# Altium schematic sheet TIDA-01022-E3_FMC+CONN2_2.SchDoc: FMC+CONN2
size 431 x 279 mm; Date: Not shown in title block; ApprovedBy: Not shown in title block; CheckedBy: Not shown in title block; Author: Not shown in title block; CompanyName: Not shown in title block; DrawnBy: Avinash N; Engineer: Not shown in title block; Organization: Not shown in title block; Address1: Not shown in title block; Address2: Not shown in title block; Address3: Not shown in title block; Address4: Not shown in title block; DocumentNumber: 1; Revision: Use project parameter SCH_Rev; SheetNumber: 20; SheetTotal: 26; PageSetup: Record=PageOptions¦CenterHorizontal=True¦CenterVertical=True¦PrintScale=1.00¦XCorrection=1.00¦YCorrection=1.00¦PrintKind=0¦BorderSize=5000000¦LeftOffset=0¦BottomOffset=0¦Orientation=2¦PaperLength=1000¦PaperWidth=1000¦Scale=100¦PaperSource=15¦PrintQuality=600¦MediaType=1¦DitherType=10¦PaperKind=Letter¦PrintScaleMode=1
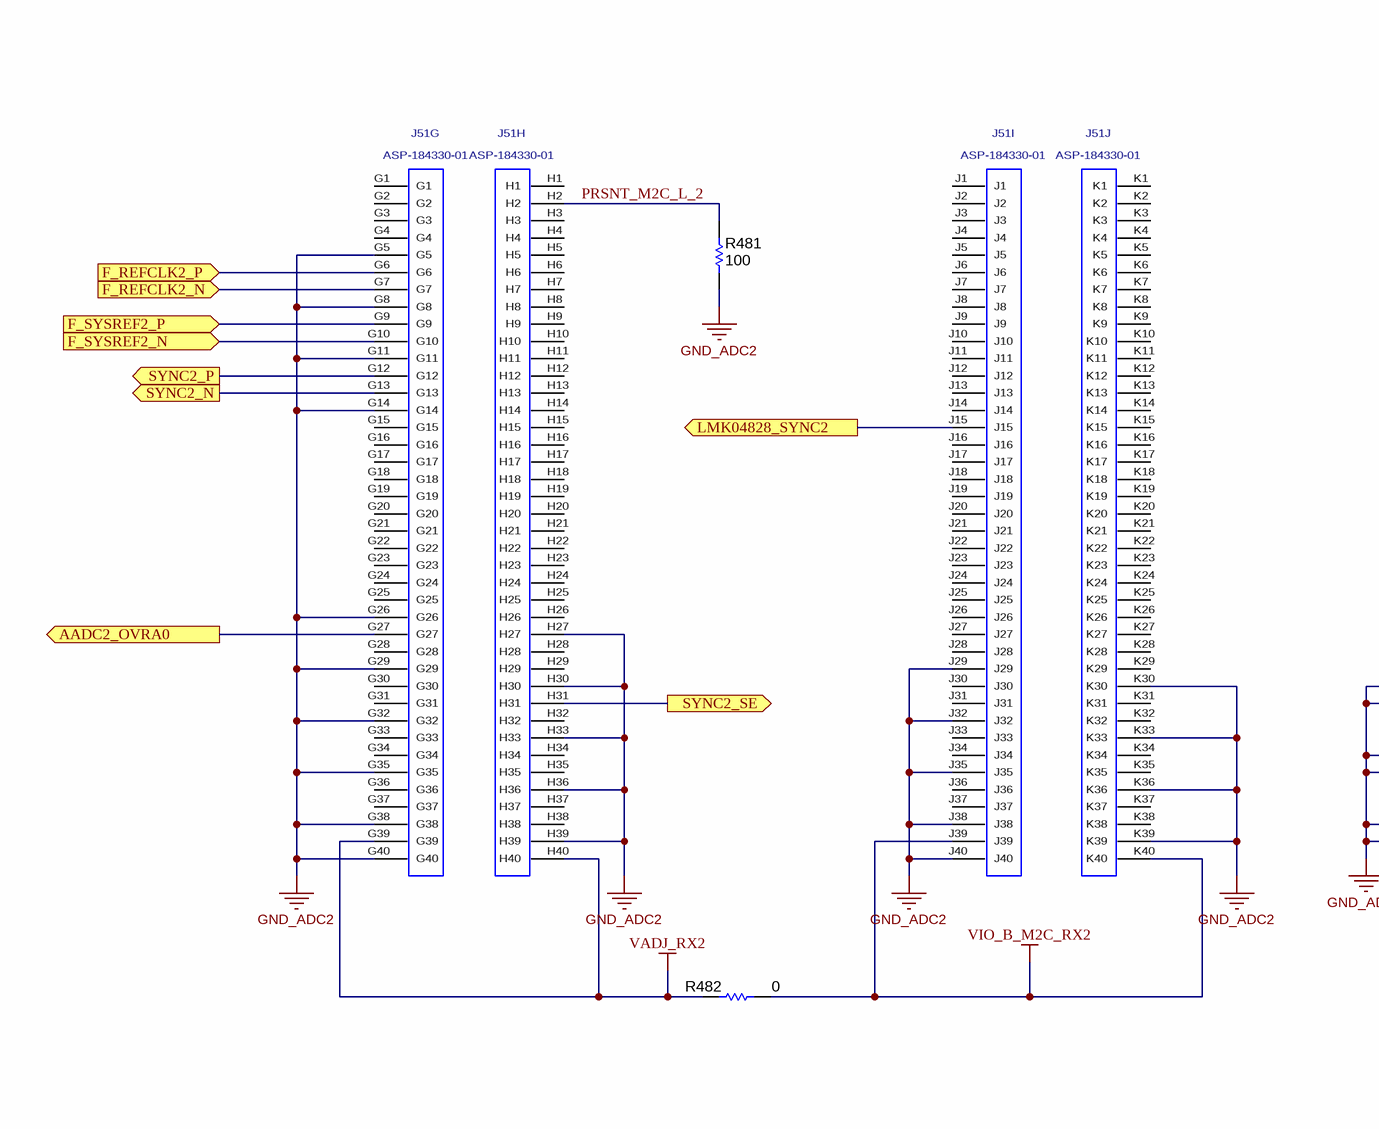
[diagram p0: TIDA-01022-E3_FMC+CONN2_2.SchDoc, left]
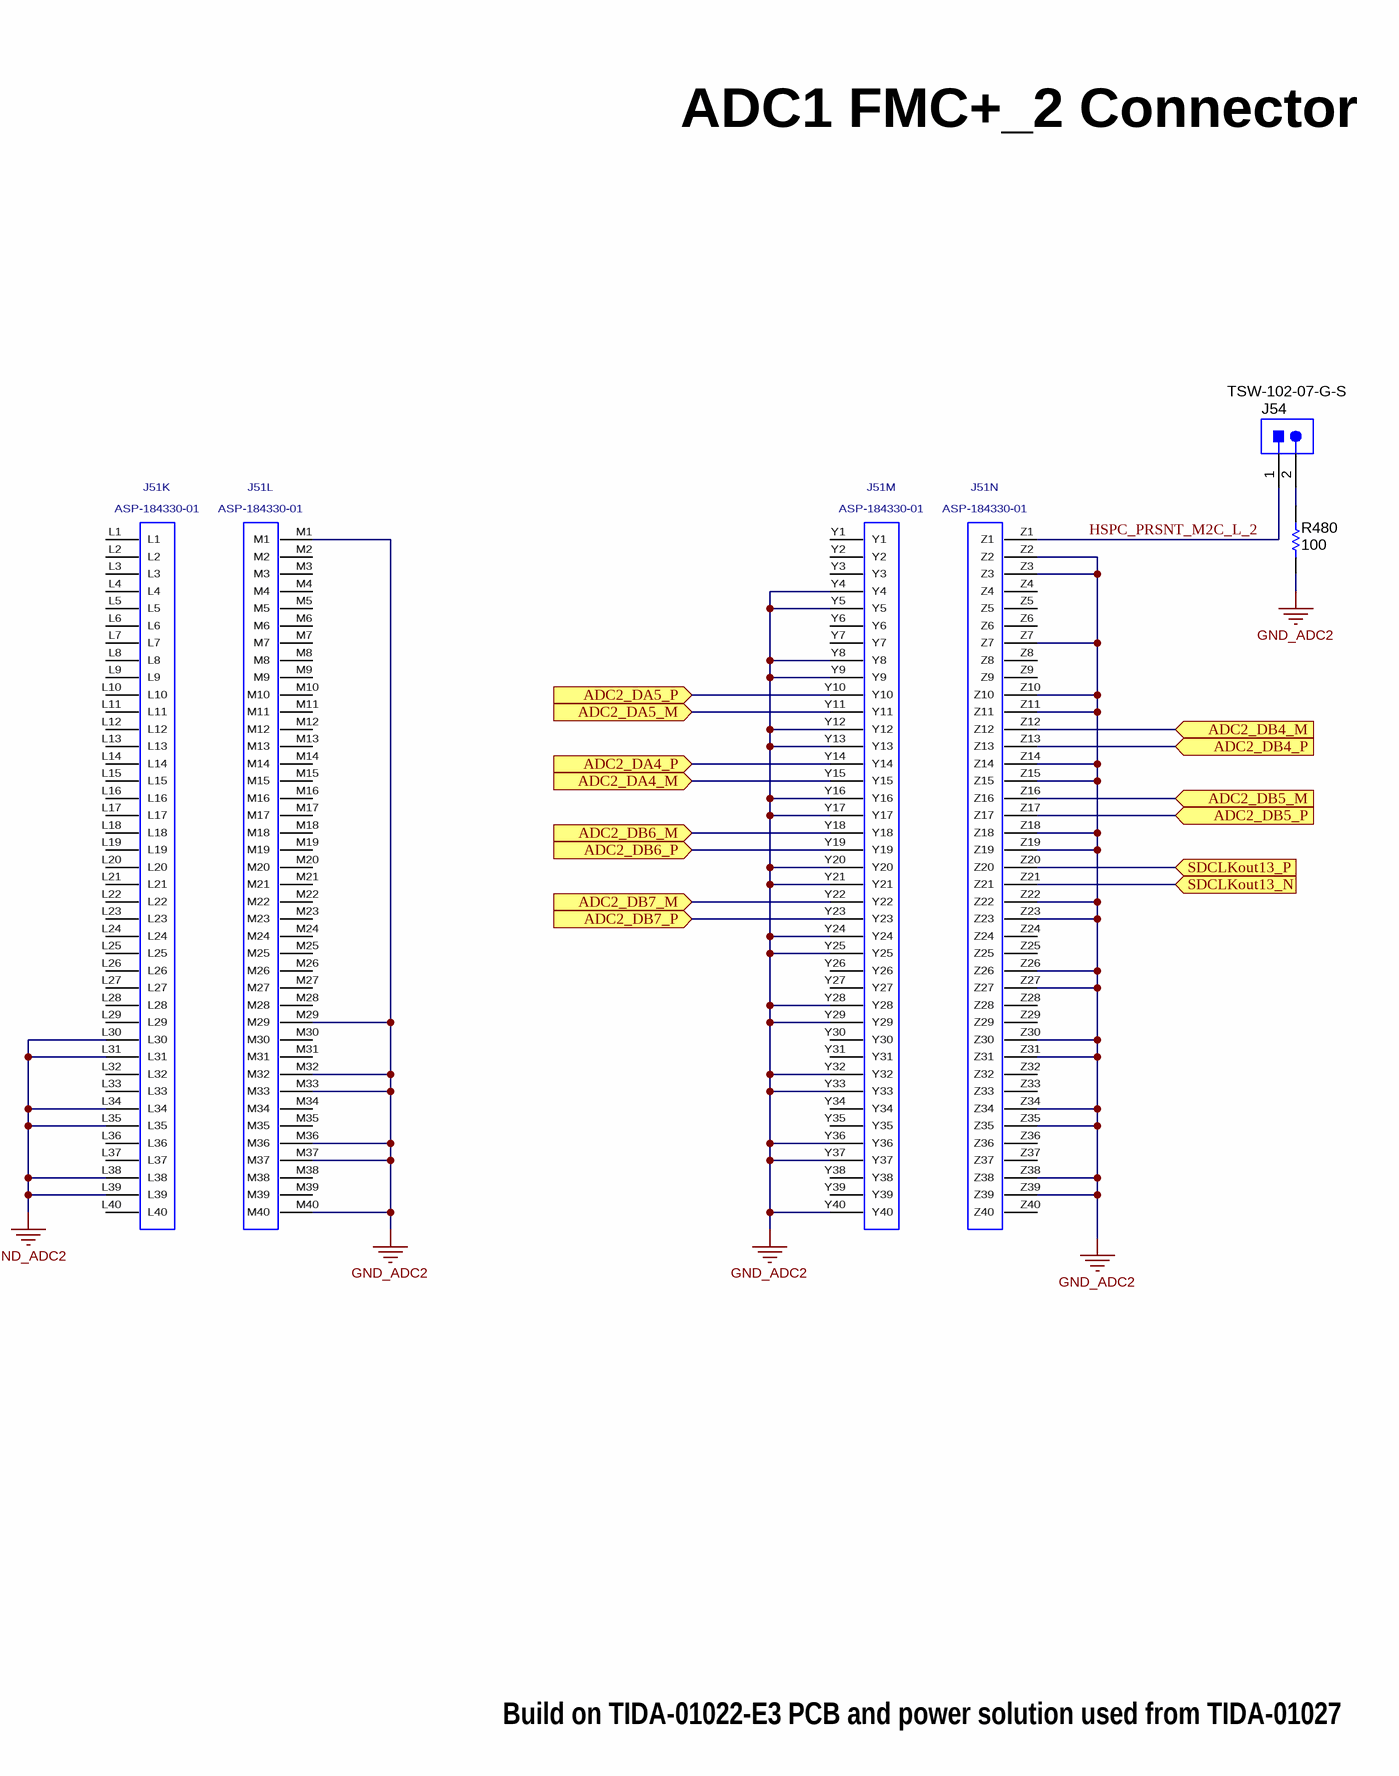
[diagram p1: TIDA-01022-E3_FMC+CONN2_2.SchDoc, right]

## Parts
J51  ASP-184330-01  [ASP-184330-01]  (parts G,H,I,J,K,L,M,N of 14)
J54  TSW-102-07-G-S  [TSW-102-07-G-S]
R480  ValueDisplayed: 100  [0402]  (hidden comment: CRCW0402100RJNED)
R481  ValueDisplayed: 100  [0402]  (hidden comment: CRCW0402100RJNED)
R482  ValueDisplayed: 0  [0402]  (hidden comment: CRCW04020000Z0ED)

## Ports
AADC2_OVRA0 (out), ADC2_DA4_M (in), ADC2_DA4_P (in), ADC2_DA5_M (in), ADC2_DA5_P (in), ADC2_DB4_M (in), ADC2_DB4_P (in), ADC2_DB5_M (in), ADC2_DB5_P (in), ADC2_DB6_M (in), ADC2_DB6_P (in), ADC2_DB7_M (in), ADC2_DB7_P (in), F_REFCLK2_N (in), F_REFCLK2_P (in), F_SYSREF2_N (in), F_SYSREF2_P (in), LMK04828_SYNC2 (out), SDCLKout13_N (in), SDCLKout13_P (in), SYNC2_N (out), SYNC2_P (out), SYNC2_SE (out)

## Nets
GND_ADC2: J51.G5 J51.G8 J51.G11 J51.G14 J51.G26 J51.G29 J51.G32 J51.G35 J51.G38 J51.G40 J51.H27 J51.H30 J51.H33 J51.H36 J51.H39 J51.J29 J51.J32 J51.J35 J51.J38 J51.J40 J51.K30 J51.K33 J51.K36 J51.K39 J51.L30 J51.L31 J51.L34 J51.L35 J51.L38 J51.L39 J51.M1 J51.M29 J51.M32 J51.M33 J51.M36 J51.M37 J51.M40 J51.Y4 J51.Y5 J51.Y8 J51.Y9 J51.Y12 J51.Y13 J51.Y16 J51.Y17 J51.Y20 J51.Y21 J51.Y24 J51.Y25 J51.Y28 J51.Y29 J51.Y32 J51.Y33 J51.Y36 J51.Y37 J51.Y40 J51.Z2 J51.Z3 J51.Z7 J51.Z10 J51.Z11 J51.Z14 J51.Z15 J51.Z18 J51.Z19 J51.Z22 J51.Z23 J51.Z26 J51.Z27 J51.Z30 J51.Z31 J51.Z34 J51.Z35 J51.Z38 J51.Z39 R480.1 R481.1
VADJ_RX2: J51.G39 J51.H40 R482.2
VIO_B_M2C_RX2: J51.J39 J51.K40 R482.1
AADC2_OVRA0: J51.G27 ; port AADC2_OVRA0
ADC2_DA4_M: J51.Y15 ; port ADC2_DA4_M
ADC2_DA4_P: J51.Y14 ; port ADC2_DA4_P
ADC2_DA5_M: J51.Y11 ; port ADC2_DA5_M
ADC2_DA5_P: J51.Y10 ; port ADC2_DA5_P
ADC2_DB4_M: J51.Z12 ; port ADC2_DB4_M
ADC2_DB4_P: J51.Z13 ; port ADC2_DB4_P
ADC2_DB5_M: J51.Z16 ; port ADC2_DB5_M
ADC2_DB5_P: J51.Z17 ; port ADC2_DB5_P
ADC2_DB6_M: J51.Y18 ; port ADC2_DB6_M
ADC2_DB6_P: J51.Y19 ; port ADC2_DB6_P
ADC2_DB7_M: J51.Y22 ; port ADC2_DB7_M
ADC2_DB7_P: J51.Y23 ; port ADC2_DB7_P
F_REFCLK2_N: J51.G7 ; port F_REFCLK2_N
F_REFCLK2_P: J51.G6 ; port F_REFCLK2_P
F_SYSREF2_N: J51.G10 ; port F_SYSREF2_N
F_SYSREF2_P: J51.G9 ; port F_SYSREF2_P
HSPC_PRSNT_M2C_L_2: J51.Z1 J54.1
LMK04828_SYNC2: J51.J15 ; port LMK04828_SYNC2
PRSNT_M2C_L_2: J51.H2 R481.2
SDCLKout13_N: J51.Z21 ; port SDCLKout13_N
SDCLKout13_P: J51.Z20 ; port SDCLKout13_P
SYNC2_N: J51.G13 ; port SYNC2_N
SYNC2_P: J51.G12 ; port SYNC2_P
SYNC2_SE: J51.H31 ; port SYNC2_SE
NetJ54_2: J54.2 R480.2

Not connected (* = marked no-connect by the designer): J51 G1 G2 G3 G4 G15 G16 G17 G18 G19 G20 G21 G22 G23 G24 G25 G28 G30 G31 G33 G34 G36 G37 H1 H3 H4 H5 H6 H7 H8 H9 H10 H11 H12 H13 H14 H15 H16 H17 H18 H19 H20 H21 H22 H23 H24 H25 H26 H28 H29 H32 H34 H35 H37 H38 J1 J2 J3 J4 J5 J6 J7 J8 J9 J10 J11 J12 J13 J14 J16 J17 J18 J19 J20 J21 J22 J23 J24 J25 J26 J27 J28 J30 J31 J33 J34 J36 J37 K1 K2 K3 K4 K5 K6 K7 K8 K9 K10 K11 K12 K13 K14 K15 K16 K17 K18 K19 K20 K21 K22 K23 K24 K25 K26 K27 K28 K29 K31 K32 K34 K35 K37 K38 L1 L2 L3 L4 L5 L6 L7 L8 L9 L10 L11 L12 L13 L14 L15 L16 L17 L18 L19 L20 L21 L22 L23 L24 L25 L26 L27 L28 L29 L32 L33 L36 L37 L40 M2 M3 M4 M5 M6 M7 M8 M9 M10 M11 M12 M13 M14 M15 M16 M17 M18 M19 M20 M21 M22 M23 M24 M25 M26 M27 M28 M30 M31 M34 M35 M38 M39 Y1 Y2 Y3 Y6 Y7 Y26 Y27 Y30 Y31 Y34 Y35 Y38 Y39 Z4 Z5 Z6 Z8 Z9 Z24 Z25 Z28 Z29 Z32 Z33 Z36 Z37 Z40

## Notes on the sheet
- ADC1 FMC+_2 Connector
- Build on TIDA-01022-E3 PCB and power solution used from TIDA-01027

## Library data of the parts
J51 = ASP-184330-01: 14 ROW .050 PITCH TERMINAL ARRAY ASM.; Manufacturer: SAMTEC
J54 = TSW-102-07-G-S: Header, 100mil, 2x1, Gold, TH; Manufacturer: Samtec; SymbolCreator: a0412235; Pitch_mm: 2.54; Gender: Male; Shrouded: N; Row_Count: 1; Current_A: 6.3; Voltage_V: 550; Cert_CSA: Y
R480 R481 = CRCW0402100RJNED: RES, 100, 5%, 0.063 W, 0402; Manufacturer: Vishay-Dale; CompType: Resistor; Value: 100; Value_Code: 100R; Tolerance_%: 5; Power_W: 0.063; Value2: 0.063W; VDC_V: 50; TempCo: 200 ppm/C; SizeArea_mm2: 0.5; SizeX_mm: 1; SizeZ_mm: 0.6; EIA_Code: E24; U/M: EA; AEC Category: Q200
R482 = CRCW04020000Z0ED: RES, 0, 5%, 0.063 W, 0402; Manufacturer: Vishay-Dale; CompType: Resistor; Value: 0; Value_Code: 0000; Tolerance_%: 5; Power_W: 0.063; Value2: 0.063W; VDC_V: 50; TempCo: 200 ppm/C; SizeArea_mm2: 0.5; SizeX_mm: 1; SizeZ_mm: 0.6; EIA_Code: E24; U/M: EA; AEC Category: Q200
